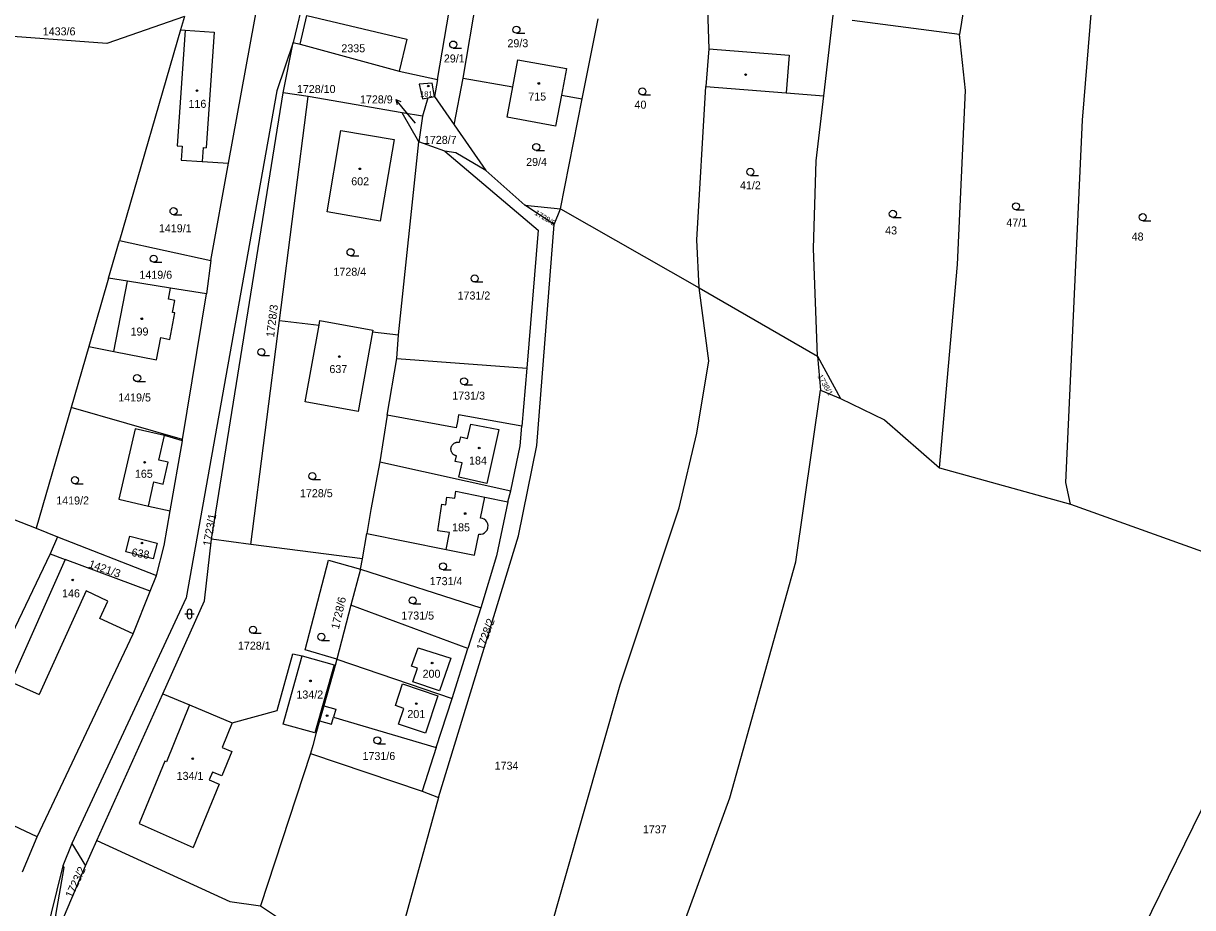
# Model space of a CAD drawing. Extents: x -725728 to -720881, y -1068679 to -1063504.
# Drawn here: x -723072.8 to -722824.4, y -1065942.2 to -1065754.4 of the extents above; entities that cross this region are included whole.
import ezdxf

# ---------------------------------------------------------------- set-up
doc = ezdxf.new("R2010")
doc.units = 0
for name, color, linetype in [('Hranice parcel', 7, 'Continuous'), ('Parcelní čísla', 7, 'Continuous'), ('Pop  PČ popisy', 7, 'Continuous'), ('Vnitřní kresba', 7, 'Continuous'), ('Značky budov', 7, 'Continuous'), ('Značky kultur', 7, 'Continuous')]:
    doc.layers.add(name, color=color, linetype=linetype)

# ---------------------------------------------------------------- blocks, each defined once
blk = doc.blocks.new('4.02_4')
at = {"layer": 'Značky budov'}
blk.add_circle((-0.001, 0), 0.0175, dxfattribs=at)
blk = doc.blocks.new('4.02_3')
at = {"layer": 'Značky budov'}
blk.add_circle((-0.001, 0), 0.0175, dxfattribs=at)
blk = doc.blocks.new('1029_188')
at = {"layer": 'Pop  PČ popisy'}
for p, q in [((0, 0), (-0.189, 0.233)), ((-0.189, 0.233), (-0.087, 0.187)), ((-0.189, 0.233), (-0.165, 0.124))]:
    blk.add_line(p, q, dxfattribs=at)
blk = doc.blocks.new('3.04_3')
at = {"layer": 'Značky kultur'}
blk.add_line((0.001, 0), (0.176, 0), dxfattribs=at)
blk.add_circle((0.001, 0.075), 0.075, dxfattribs=at)
blk = doc.blocks.new('3.04_2')
at = {"layer": 'Značky kultur'}
blk.add_line((0.001, 0), (0.176, 0), dxfattribs=at)
blk.add_circle((0.001, 0.075), 0.075, dxfattribs=at)
blk = doc.blocks.new('3.16_2')
at = {"layer": 'Značky kultur'}
for p, q in [((-0.1, 0.1), (0.1, 0.1)), ((-0.05, 0.15), (-0.05, 0.05)), ((0.05, 0.05), (0.05, 0.15))]:
    blk.add_line(p, q, dxfattribs=at)
for centre, start, end in [((0, 0.15), 0, 180), ((0, 0.05), 180, 359.9879)]:
    blk.add_arc(centre, 0.05, start, end, dxfattribs=at)

msp = doc.modelspace()

# ---------------------------------------------------------------- linework, layer by layer
at = {"layer": 'Hranice parcel'}
for p, q in [((-722871.96, -1065744.84), (-722873.91, -1065756.75)), ((-723029.24, -1065784.12), (-723022.58, -1065747.46)), ((-722984.85, -1065766.34), (-722981.58, -1065747.29)), ((-722979.38, -1065766.03), (-722976.37, -1065748.32)), ((-723038.6, -1065752.93), (-723039.44, -1065755.81)), ((-722902.79, -1065769.77), (-722900.78, -1065752.66)), ((-723039.44, -1065755.81), (-723052.41, -1065800.51)), ((-722954.11, -1065770.46), (-722950.73, -1065753.42)), ((-722873.91, -1065756.75), (-722896.74, -1065753.82)), ((-723017.65, -1065769.13), (-723015.49, -1065758.45)), ((-723015.49, -1065758.45), (-723014.04, -1065758.84)), ((-723014.04, -1065758.84), (-722992.98, -1065764.54)), ((-722992.98, -1065764.54), (-722984.85, -1065766.34)), ((-722984.85, -1065766.34), (-722985.46, -1065769.92)), ((-722981.3, -1065775.96), (-722979.38, -1065766.03)), ((-722979.38, -1065766.03), (-722968.86, -1065767.87)), ((-723032.86, -1065863.96), (-723017.65, -1065769.13)), ((-723018.43, -1065817.49), (-723012.34, -1065769.91)), ((-723012.34, -1065769.91), (-723017.65, -1065769.13)), ((-722992.36, -1065773.38), (-723012.34, -1065769.91)), ((-722986.9, -1065770.21), (-722988.07, -1065774.13)), ((-722986.9, -1065770.21), (-722985.46, -1065769.92)), ((-722985.46, -1065769.92), (-722981.3, -1065775.96)), ((-722958.74, -1065793.79), (-722954.11, -1065770.46)), ((-722958.53, -1065769.68), (-722954.11, -1065770.46)), ((-722988.81, -1065779.57), (-722992.36, -1065773.38)), ((-722988.07, -1065774.13), (-722992.36, -1065773.38)), ((-722988.07, -1065774.13), (-722988.81, -1065779.57)), ((-722981.3, -1065775.96), (-722974.61, -1065785.67)), ((-722993.12, -1065820.55), (-722988.81, -1065779.57)), ((-722983.28, -1065781.56), (-722988.81, -1065779.57)), ((-723033, -1065804.79), (-723029.24, -1065784.12)), ((-722974.61, -1065785.67), (-722966.3, -1065793.05)), ((-722960.07, -1065797.09), (-722966.3, -1065793.05)), ((-722966.3, -1065793.05), (-722958.74, -1065793.79)), ((-722960.07, -1065797.09), (-722958.74, -1065793.79)), ((-722958.74, -1065793.79), (-722929.22, -1065810.56)), ((-723054.73, -1065808.5), (-723052.41, -1065800.51)), ((-723052.41, -1065800.51), (-723033, -1065804.79)), ((-723033, -1065804.79), (-723033.95, -1065811.84)), ((-723054.73, -1065808.5), (-723058.95, -1065823.06)), ((-723033.95, -1065811.84), (-723041.58, -1065810.61)), ((-723039.01, -1065842.78), (-723033.95, -1065811.84)), ((-722929.22, -1065810.56), (-722904.11, -1065825.11)), ((-723024.52, -1065865.08), (-723018.43, -1065817.49)), ((-723018.43, -1065817.49), (-723010.01, -1065818.51)), ((-722998.64, -1065819.88), (-722993.12, -1065820.55)), ((-722993.49, -1065825.57), (-722993.12, -1065820.55)), ((-723058.95, -1065823.06), (-723062.69, -1065835.96)), ((-722904.11, -1065825.11), (-722899.24, -1065834.1)), ((-722904.11, -1065825.11), (-722903.49, -1065832.33)), ((-722995.51, -1065837.62), (-722993.49, -1065825.57)), ((-722993.49, -1065825.57), (-722965.9, -1065827.6)), ((-722965.9, -1065827.6), (-722966.94, -1065839.96)), ((-722903.49, -1065832.33), (-722899.24, -1065834.1)), ((-723062.69, -1065835.96), (-723070.14, -1065861.63)), ((-723039.01, -1065842.78), (-723062.69, -1065835.96)), ((-722995.51, -1065837.62), (-722997.09, -1065847.51)), ((-723112.41, -1065845.03), (-723070.14, -1065861.63)), ((-723041.66, -1065857.96), (-723039.06, -1065843.06)), ((-723039.06, -1065843.06), (-723039.01, -1065842.78)), ((-722997.09, -1065847.51), (-722969.29, -1065853.65)), ((-722878.16, -1065848.82), (-722850.33, -1065856.48)), ((-722969.9, -1065856.03), (-722969.29, -1065853.65)), ((-722850.33, -1065856.48), (-722822.29, -1065866.55)), ((-723070.14, -1065861.63), (-723065.57, -1065863.42)), ((-723065.57, -1065863.42), (-723067.18, -1065867.04)), ((-723065.57, -1065863.42), (-723044.58, -1065871.66)), ((-723024.52, -1065865.08), (-723032.86, -1065863.96)), ((-723000.81, -1065868.12), (-723024.52, -1065865.08)), ((-723000.81, -1065868.12), (-722999.84, -1065862.74)), ((-723067.18, -1065867.04), (-723121.57, -1065981.06)), ((-723067.18, -1065867.04), (-723063.99, -1065868.23)), ((-723045.91, -1065874.98), (-723063.99, -1065868.23)), ((-723001.2, -1065870.28), (-723000.81, -1065868.12)), ((-723045.91, -1065874.98), (-723044.58, -1065871.66)), ((-723001.2, -1065870.28), (-723003.24, -1065877.99)), ((-723001.2, -1065870.28), (-722975.63, -1065878.52)), ((-723003.24, -1065877.99), (-723006.27, -1065889.46)), ((-722978.39, -1065887.13), (-723003.24, -1065877.99)), ((-722975.63, -1065878.52), (-722978.39, -1065887.13)), ((-722981.74, -1065897.78), (-722978.39, -1065887.13)), ((-723013.59, -1065888.7), (-723006.84, -1065890.61)), ((-723006.27, -1065889.46), (-723006.59, -1065890.76)), ((-723006.27, -1065889.46), (-722981.74, -1065897.78)), ((-723006.84, -1065890.61), (-723006.59, -1065890.76)), ((-723057.23, -1065927.92), (-723043.23, -1065896.79)), ((-722985.15, -1065908.16), (-722981.74, -1065897.78)), ((-723011.86, -1065909.47), (-723022.47, -1065941.8)), ((-723011.86, -1065909.47), (-722988.13, -1065917.44)), ((-722985.15, -1065908.16), (-722988.13, -1065917.44)), ((-722984.62, -1065918.83), (-722995.45, -1065957.96)), ((-722988.13, -1065917.44), (-722984.62, -1065918.83)), ((-723062.54, -1065928.58), (-723064.44, -1065933.34)), ((-723062.54, -1065928.58), (-723059.67, -1065933.35)), ((-723059.67, -1065933.35), (-723057.23, -1065927.92))]:
    msp.add_line(p, q, dxfattribs=at)
for points in [[(-722977.87, -1065692.96), (-722980.37, -1065698.39), (-722992.27, -1065715.88), (-723003.85, -1065732.87), (-723011.89, -1065744.73), (-723013.02, -1065748.09), (-723015.49, -1065758.45)], [(-722850.33, -1065856.48), (-722851.34, -1065851.92), (-722847.81, -1065774.96), (-722845.54, -1065747.25)], [(-722927.53, -1065749.23), (-722927.2, -1065759.83), (-722927.83, -1065767.78)], [(-723038.6, -1065752.93), (-723055.13, -1065758.65), (-723081.85, -1065756.69), (-723097.93, -1065751.48)], [(-723014.04, -1065758.84), (-723012.58, -1065752.71), (-722991.36, -1065757.76), (-722992.98, -1065764.54)], [(-723039.44, -1065755.81), (-723038.47, -1065755.88), (-723040.14, -1065780.42), (-723039.14, -1065780.49), (-723039.34, -1065783.43), (-723034.85, -1065783.74), (-723029.24, -1065784.12)], [(-722878.16, -1065848.82), (-722874.38, -1065805.65), (-722872.63, -1065768.68), (-722873.91, -1065756.75)], [(-723015.49, -1065758.45), (-723018.98, -1065768.72), (-723038.27, -1065876.38), (-723062.54, -1065928.58)], [(-722968.86, -1065767.87), (-722967.79, -1065762.12), (-722957.47, -1065763.97), (-722958.53, -1065769.68)], [(-722985.46, -1065769.92), (-722985.98, -1065767.1), (-722988.77, -1065767.35), (-722988.06, -1065770.44), (-722986.9, -1065770.21)], [(-722958.53, -1065769.68), (-722959.75, -1065776.23), (-722970.05, -1065774.36), (-722968.86, -1065767.87)], [(-722929.22, -1065810.56), (-722929.75, -1065800.41), (-722927.83, -1065767.78)], [(-722927.83, -1065767.78), (-722910.78, -1065769.13), (-722902.79, -1065769.77)], [(-722904.11, -1065825.11), (-722904.97, -1065802.19), (-722904.41, -1065783.59), (-722902.79, -1065769.77)], [(-722994.06, -1065779.09), (-722997.05, -1065796.42), (-723008.32, -1065794.43), (-723005.36, -1065777.14), (-722994.06, -1065779.09)], [(-722974.61, -1065785.67), (-722980.96, -1065781.92), (-722983.28, -1065781.56)], [(-722983.28, -1065781.56), (-722963.43, -1065798.29), (-722965.9, -1065827.6)], [(-722984.62, -1065918.83), (-722967.65, -1065863.21), (-722963.72, -1065844.05), (-722960.07, -1065797.09)], [(-723041.58, -1065810.61), (-723050.72, -1065809.14), (-723054.73, -1065808.5)], [(-723058.95, -1065823.06), (-723053.62, -1065824.09), (-723044.54, -1065825.85), (-723043.63, -1065821.14), (-723041.71, -1065821.51), (-723040.63, -1065815.91), (-723041.17, -1065815.81), (-723040.67, -1065813.26), (-723042.04, -1065812.99), (-723041.58, -1065810.61)], [(-722984.86, -1066030.98), (-722946.02, -1065894.85), (-722933.51, -1065857.3), (-722929.71, -1065841.4), (-722927.18, -1065826.07), (-722929.22, -1065810.56)], [(-723010.01, -1065818.51), (-723009.83, -1065817.51), (-722998.58, -1065819.54), (-722998.64, -1065819.88)], [(-722998.64, -1065819.88), (-723001.68, -1065836.86), (-723012.96, -1065834.76), (-723010.01, -1065818.51)], [(-722952.48, -1066035.62), (-722940.39, -1065967.06), (-722922.73, -1065918.87), (-722908.72, -1065868.75), (-722903.49, -1065832.33)], [(-722899.24, -1065834.1), (-722889.85, -1065838.6), (-722878.16, -1065848.82)], [(-722966.94, -1065839.96), (-722980.36, -1065837.52), (-722980.62, -1065838.98), (-722980.86, -1065840.29), (-722995.51, -1065837.62)], [(-722969.29, -1065853.65), (-722967.29, -1065844.13), (-722966.94, -1065839.96)], [(-723039.06, -1065843.06), (-723042.87, -1065841.92), (-723049.11, -1065840.5), (-723052.53, -1065855.48), (-723046.29, -1065856.91), (-723041.66, -1065857.96)], [(-722997.09, -1065847.51), (-722997.7, -1065850.5), (-722999.01, -1065857.65), (-722999.84, -1065862.74)], [(-722975.73, -1065859.47), (-722974.81, -1065855.01), (-722969.9, -1065856.03)], [(-722969.9, -1065856.03), (-722972.3, -1065867.47), (-722975.63, -1065878.52)], [(-723044.58, -1065871.66), (-723042.94, -1065865.32), (-723041.66, -1065857.96)], [(-722976.07, -1065862.87), (-722975.66, -1065862.88), (-722975.25, -1065862.8), (-722974.88, -1065862.61), (-722974.56, -1065862.35), (-722974.32, -1065862.02), (-722974.16, -1065861.63), (-722974.13, -1065861.48), (-722974.1, -1065861.06), (-722974.18, -1065860.66), (-722974.36, -1065860.28), (-722974.61, -1065859.96), (-722974.94, -1065859.71), (-722975.32, -1065859.54), (-722975.73, -1065859.47)], [(-723045.25, -1065868.12), (-723051.07, -1065866.64), (-723050.23, -1065863.34), (-723044.41, -1065864.82), (-723045.25, -1065868.12)], [(-723043.23, -1065896.79), (-723034.34, -1065877.01), (-723032.86, -1065863.96)], [(-722999.84, -1065862.74), (-722983.03, -1065866.13), (-722976.97, -1065867.35), (-722976.07, -1065862.87)], [(-723063.99, -1065868.23), (-723075.51, -1065894.21), (-723077.32, -1065893.39), (-723079.87, -1065899.01), (-723092.36, -1065925.57)], [(-723006.27, -1065889.46), (-723012.95, -1065887.44), (-723007.99, -1065868.43), (-723001.2, -1065870.28)], [(-723073, -1065934.58), (-723069.92, -1065927.18), (-723049.55, -1065884.06), (-723045.91, -1065874.98)], [(-722838.33, -1065953.62), (-722817.28, -1065910.76), (-722812.2, -1065898.91), (-722803.63, -1065873)], [(-723043.23, -1065896.79), (-723037.52, -1065899.16), (-723028.45, -1065902.92), (-723018.94, -1065900.31), (-723015.57, -1065888.27), (-723013.59, -1065888.7)], [(-723006.84, -1065890.61), (-723010.94, -1065905.09), (-723017.66, -1065903.21), (-723013.59, -1065888.7)], [(-723006.59, -1065890.76), (-723009.03, -1065899.36), (-723009.91, -1065902.5)], [(-723009.91, -1065902.5), (-723007.36, -1065903.21), (-723006.95, -1065901.74), (-722985.15, -1065908.16)], [(-723009.91, -1065902.5), (-723010.67, -1065905.25), (-723011.37, -1065907.74), (-723011.86, -1065909.47)], [(-723057.23, -1065927.92), (-723029.01, -1065940.92), (-723022.47, -1065941.8)], [(-723064.44, -1065933.34), (-723079.47, -1065993.88), (-723086.42, -1066030.05), (-723087.85, -1066077.8)], [(-723064.44, -1065933.34), (-723064.26, -1065933.66), (-723066.03, -1065943.77), (-723065.19, -1065946.36)], [(-723064.4, -1065944.5), (-723064.13, -1065943.87), (-723059.67, -1065933.35)], [(-723022.47, -1065941.8), (-723013.77, -1065947.58), (-723016.86, -1065965.65)]]:
    msp.add_lwpolyline(points, dxfattribs=at)
at = {"layer": 'Pop  PČ popisy'}
msp.add_line((-722989.55, -1065775.62), (-722991.8, -1065772.88), dxfattribs=at)
at = {"layer": 'Vnitřní kresba'}
for p, q in [((-723038.47, -1065755.88), (-723032.34, -1065756.3)), ((-723032.34, -1065756.3), (-723034.01, -1065780.84)), ((-722927.2, -1065759.83), (-722910.15, -1065761.19)), ((-722910.15, -1065761.19), (-722910.78, -1065769.13)), ((-723034.65, -1065780.8), (-723034.85, -1065783.74)), ((-723034.65, -1065780.8), (-723034.01, -1065780.84)), ((-723053.62, -1065824.09), (-723050.72, -1065809.14)), ((-722978.44, -1065842.54), (-722977.76, -1065839.52)), ((-722977.76, -1065839.52), (-722971.85, -1065840.64)), ((-723044.06, -1065847.14), (-723042.87, -1065841.92)), ((-722980.17, -1065843.38), (-722979.91, -1065842.21)), ((-722979.91, -1065842.21), (-722978.44, -1065842.54)), ((-722971.85, -1065840.64), (-722974.4, -1065852.12)), ((-723042.07, -1065847.59), (-723044.06, -1065847.14)), ((-723043.13, -1065852.24), (-723042.07, -1065847.59)), ((-722981.08, -1065847.43), (-722980.82, -1065846.26)), ((-722979.62, -1065847.76), (-722981.08, -1065847.43)), ((-722980.3, -1065850.78), (-722979.62, -1065847.76)), ((-723046.29, -1065856.91), (-723045.12, -1065851.79)), ((-723045.12, -1065851.79), (-723043.13, -1065852.24)), ((-722974.4, -1065852.12), (-722980.3, -1065850.78)), ((-722983.11, -1065856.65), (-722982.85, -1065855)), ((-722982.85, -1065855), (-722981.2, -1065855.25)), ((-722981.2, -1065855.25), (-722980.97, -1065853.74)), ((-722980.97, -1065853.74), (-722974.81, -1065855.01)), ((-722984.79, -1065862.17), (-722983.93, -1065856.53)), ((-722983.93, -1065856.53), (-722983.11, -1065856.65)), ((-722982.31, -1065862.55), (-722984.79, -1065862.17)), ((-722983.03, -1065866.13), (-722982.31, -1065862.55)), ((-723059.5, -1065874.94), (-723069.49, -1065896.95)), ((-723054.91, -1065877.09), (-723059.5, -1065874.94)), ((-723056.62, -1065880.76), (-723054.91, -1065877.09)), ((-723049.55, -1065884.06), (-723056.62, -1065880.76)), ((-722990.37, -1065890.93), (-722988.97, -1065886.99)), ((-722988.97, -1065886.99), (-722982.05, -1065889.19)), ((-722982.05, -1065889.19), (-722984.4, -1065896.17)), ((-722989.13, -1065891.35), (-722990.37, -1065890.93)), ((-722990.11, -1065894.25), (-722989.13, -1065891.35)), ((-723075.51, -1065894.21), (-723069.49, -1065896.95)), ((-722993.79, -1065899.28), (-722992.27, -1065894.7)), ((-722992.27, -1065894.7), (-722984.76, -1065897.23)), ((-722984.4, -1065896.17), (-722990.11, -1065894.25)), ((-722984.76, -1065897.23), (-722987.43, -1065905.17)), ((-723037.52, -1065899.16), (-723042.41, -1065911.24)), ((-723009.03, -1065899.36), (-723006.48, -1065900.07)), ((-722992.03, -1065899.87), (-722993.79, -1065899.28)), ((-722993.17, -1065903.24), (-722992.03, -1065899.87)), ((-723006.48, -1065900.07), (-723006.95, -1065901.74)), ((-723028.45, -1065902.92), (-723030.64, -1065908.2)), ((-722987.43, -1065905.17), (-722993.17, -1065903.24)), ((-723028.58, -1065909.06), (-723030.71, -1065914.2)), ((-723030.64, -1065908.2), (-723028.58, -1065909.06)), ((-723042.78, -1065911.09), (-723048.25, -1065924.29)), ((-723042.41, -1065911.24), (-723042.78, -1065911.09)), ((-723032.67, -1065913.39), (-723033.37, -1065915.07)), ((-723030.71, -1065914.2), (-723032.67, -1065913.39)), ((-723031.22, -1065915.96), (-723036.8, -1065929.43)), ((-723033.37, -1065915.07), (-723031.22, -1065915.96)), ((-723069.92, -1065927.18), (-723077.42, -1065923.64)), ((-723048.25, -1065924.29), (-723036.8, -1065929.43))]:
    msp.add_line(p, q, dxfattribs=at)
msp.add_lwpolyline([(-722980.82, -1065846.26), (-722980.92, -1065846.23), (-722981.02, -1065846.2), (-722981.12, -1065846.16), (-722981.22, -1065846.11), (-722981.31, -1065846.06), (-722981.4, -1065846), (-722981.48, -1065845.93), (-722981.56, -1065845.86), (-722981.63, -1065845.78), (-722981.7, -1065845.7), (-722981.76, -1065845.61), (-722981.81, -1065845.52), (-722981.86, -1065845.43), (-722981.9, -1065845.33), (-722981.93, -1065845.23), (-722981.96, -1065845.12), (-722981.98, -1065845.02), (-722981.99, -1065844.91), (-722981.99, -1065844.81), (-722981.99, -1065844.7), (-722981.97, -1065844.59), (-722981.96, -1065844.49), (-722981.93, -1065844.39), (-722981.89, -1065844.29), (-722981.85, -1065844.19), (-722981.8, -1065844.09), (-722981.75, -1065844), (-722981.69, -1065843.92), (-722981.62, -1065843.83), (-722981.55, -1065843.76), (-722981.47, -1065843.69), (-722981.38, -1065843.62), (-722981.3, -1065843.56), (-722981.2, -1065843.51), (-722981.11, -1065843.46), (-722981.01, -1065843.42), (-722980.91, -1065843.39), (-722980.8, -1065843.37), (-722980.7, -1065843.35), (-722980.59, -1065843.34), (-722980.49, -1065843.34), (-722980.38, -1065843.34), (-722980.27, -1065843.36), (-722980.17, -1065843.38)], dxfattribs=at)

# ---------------------------------------------------------------- block references
at = {"layer": 'Pop  PČ popisy', "xscale": 10, "yscale": 10}
msp.add_blockref('1029_188', (-722991.8, -1065772.88), dxfattribs=at)
at = {"layer": 'Značky budov', "xscale": 10, "yscale": 10}
for name, p in [('4.02_3', (-722919.36, -1065765.29)), ('4.02_3', (-722986.79, -1065767.71)), ('4.02_4', (-722963.31, -1065767.17)), ('4.02_3', (-723035.94, -1065768.69)), ('4.02_3', (-723001.36, -1065785.3)), ('4.02_4', (-723047.67, -1065817.15)), ('4.02_4', (-723005.7, -1065825.17)), ('4.02_3', (-722975.97, -1065844.59)), ('4.02_3', (-723047.07, -1065847.62)), ('4.02_3', (-722978.96, -1065858.51)), ('4.02_3', (-723047.64, -1065864.76)), ('4.02_3', (-723062.36, -1065872.61)), ('4.02_3', (-722985.99, -1065890.25)), ('4.02_3', (-723011.83, -1065894.04)), ('4.02_3', (-722989.34, -1065898.87)), ('4.02_3', (-723008.3, -1065901.44)), ('4.02_3', (-723036.85, -1065910.57))]:
    msp.add_blockref(name, p, dxfattribs=at)
at = {"layer": 'Značky kultur', "xscale": 10, "yscale": 10}
for name, p in [('3.04_2', (-722968.08, -1065756.51)), ('3.04_3', (-722981.52, -1065759.66)), ('3.04_2', (-722941.32, -1065769.62)), ('3.04_3', (-722963.88, -1065781.41)), ('3.04_3', (-722918.38, -1065786.68)), ('3.04_2', (-722861.95, -1065794)), ('3.04_2', (-723040.95, -1065795.04)), ('3.04_2', (-722888.1, -1065795.61)), ('3.04_2', (-722835.01, -1065796.32)), ('3.04_2', (-723003.33, -1065803.76)), ('3.04_3', (-723045.18, -1065805.14)), ('3.04_2', (-722976.96, -1065809.33)), ('3.04_2', (-723022.28, -1065824.97)), ('3.04_2', (-723048.68, -1065830.49)), ('3.04_3', (-722979.2, -1065831.16)), ('3.04_2', (-723011.44, -1065851.3)), ('3.04_3', (-723061.9, -1065852.17)), ('3.04_2', (-722983.68, -1065870.46)), ('3.04_2', (-722990.13, -1065877.7)), ('3.16_2', (-723037.54, -1065880.83)), ('3.04_2', (-723024.06, -1065883.94)), ('3.04_3', (-723009.54, -1065885.43)), ('3.04_3', (-722997.63, -1065907.42))]:
    msp.add_blockref(name, p, dxfattribs=at)

# ---------------------------------------------------------------- texts
at = {"layer": 'Parcelní čísla'}
for s, height, p in [('1433/6', 1.7, (-723068.73, -1065756.96)), ('29/3', 1.7, (-722969.99, -1065759.48)), ('2335', 1.7, (-723005.28, -1065760.55)), ('29/1', 1.7, (-722983.5, -1065762.71)), ('1728/10', 1.7, (-723014.73, -1065769.2)), ('116', 1.7, (-723037.76, -1065772.35)), ('1728/9', 1.7, (-723001.32, -1065771.41)), ('181', 1.14, (-722988.54, -1065769.97)), ('715', 1.7, (-722965.56, -1065770.79)), ('40', 1.7, (-722942.99, -1065772.52)), ('1728/7', 1.7, (-722987.74, -1065780)), ('29/4', 1.7, (-722966.01, -1065784.69)), ('602', 1.7, (-723003.18, -1065788.8)), ('41/2', 1.7, (-722920.58, -1065789.66)), ('1419/1', 1.7, (-723044.05, -1065798.78)), ('43', 1.7, (-722889.73, -1065799.23)), ('47/1', 1.7, (-722863.97, -1065797.55)), ('48', 1.7, (-722837.35, -1065800.53)), ('1419/6', 1.7, (-723048.19, -1065808.64)), ('1728/4', 1.7, (-723006.96, -1065808)), ('1731/2', 1.7, (-722980.59, -1065813.05)), ('199', 1.7, (-723050.06, -1065820.7)), ('637', 1.7, (-723007.82, -1065828.67)), ('1731/3', 1.7, (-722981.71, -1065834.31)), ('1419/5', 1.7, (-723052.69, -1065834.7)), ('184', 1.7, (-722978.15, -1065848.09)), ('165', 1.7, (-723049.15, -1065850.91)), ('1419/2', 1.7, (-723065.86, -1065856.58)), ('1728/5', 1.7, (-723014.07, -1065855.03)), ('185', 1.7, (-722981.74, -1065862.28)), ('1731/4', 1.7, (-722986.5, -1065873.71)), ('146', 1.7, (-723064.63, -1065876.3)), ('1731/5', 1.7, (-722992.53, -1065881.01)), ('1728/1', 1.7, (-723027.25, -1065887.41)), ('200', 1.7, (-722988.02, -1065893.37)), ('134/2', 1.7, (-723014.83, -1065897.79)), ('201', 1.7, (-722991.25, -1065901.93)), ('1731/6', 1.7, (-723000.78, -1065910.84)), ('1734', 1.7, (-722972.7, -1065912.89)), ('134/1', 1.7, (-723040.28, -1065915.06)), ('1737', 1.7, (-722941.21, -1065926.42))]:
    msp.add_text(s, height=height, dxfattribs=at).set_placement(p)
for s, height, rotation, p in [('1728/8', 1.14, 329, (-722964.33, -1065794.96)), ('1728/3', 1.7, 83, (-723019.58, -1065821.14)), ('1738/1', 1.14, 300, (-722904.14, -1065829.37)), ('1723/1', 1.7, 80, (-723033.03, -1065865.54)), ('638', 1.7, 350, (-723049.97, -1065867.5)), ('1421/3', 1.7, 341, (-723059.13, -1065869.9)), ('1728/6', 1.7, 77, (-723005.82, -1065883.2)), ('1728/2', 1.7, 70, (-722975.03, -1065887.72)), ('1723/2', 1.7, 65, (-723062.48, -1065940.3))]:
    msp.add_text(s, height=height, rotation=rotation, dxfattribs=at).set_placement(p)

doc.saveas('drawing.dxf')
